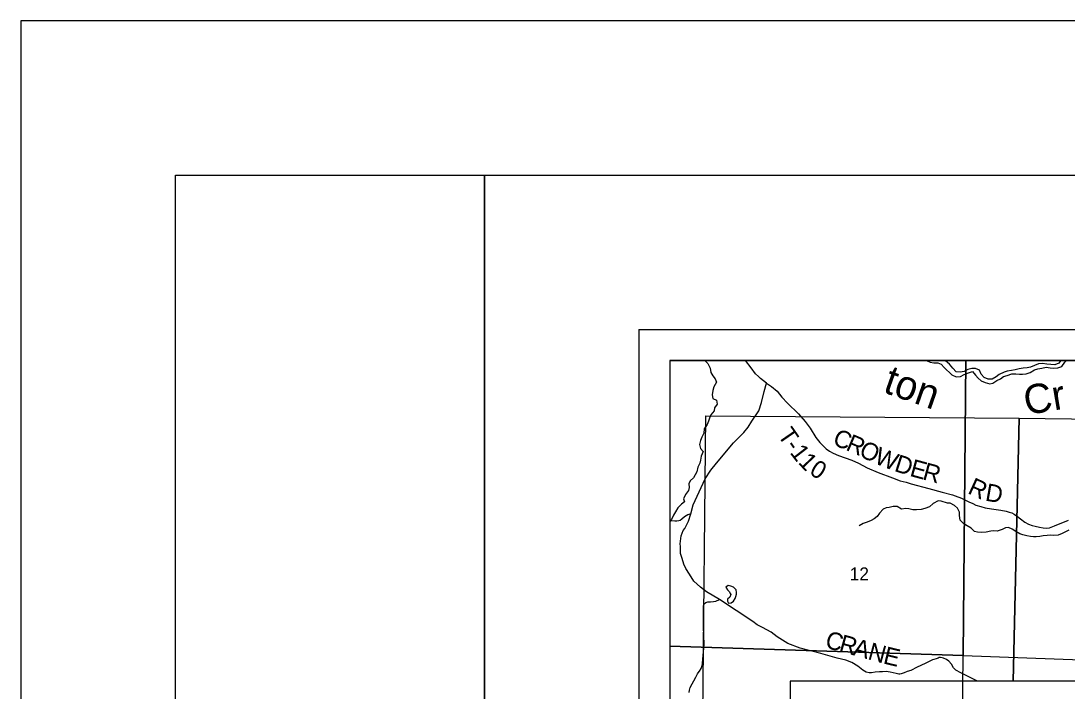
# Model space of a CAD drawing. Extents: x -19.9 to 41.9, y 0 to 32.3.
# Drawn here: x 0 to 3.386, y 19.829 to 22 of the extents above; entities that cross this region are included whole.
import ezdxf

# ---------------------------------------------------------------- set-up
doc = ezdxf.new("R2010")
doc.units = 0
for name, color, linetype in [('GM_X_Corporation', 7, 'Continuous'), ('GM_X_Major_River', 7, 'Continuous'), ('GM_X_Major_River_Text', 7, 'Continuous'), ('GM_X_Minor_Lake', 7, 'Continuous'), ('GM_X_Minor_River', 7, 'Continuous'), ('GM_X_Section', 7, 'Continuous'), ('GM_X_Section_Text', 7, 'Continuous'), ('GM_X_Township_Road', 7, 'Continuous'), ('GM_X_Township_Road_Text', 7, 'Continuous'), ('SH_Border', 7, 'Continuous'), ('SH_Cut_Line', 7, 'Continuous'), ('SH_Data', 7, 'Continuous'), ('SH_Text', 7, 'Continuous')]:
    doc.layers.add(name, color=color, linetype=linetype)

msp = doc.modelspace()

# ---------------------------------------------------------------- linework, layer by layer
at = {"layer": 'GM_X_Corporation'}
for points in [[(8.9, 17.8974), (8.9, 20.9), (2.1, 20.9), (2.1, 17.918), (2.4715, 17.9106), (2.973, 17.9007), (3.7505, 17.884), (3.984, 17.879), (4.2613, 17.8672), (4.9169, 17.8392), (5.0192, 17.8403), (5.0257, 17.9637), (5.4954, 17.9559), (5.761, 17.9543), (5.9048, 17.9534), (6.2397, 17.9517), (6.2497, 17.9517), (6.3069, 17.9505), (6.7, 17.9422), (6.9468, 17.937), (7.3858, 17.9277), (7.5529, 17.9242), (7.9072, 17.9171)], [(3.0583, 20.9), (2.1, 20.9), (2.1, 19.9743), (3.0491, 19.9448)], [(4.0724, 20.9), (3.0583, 20.9), (3.0491, 19.9448), (4.0503, 19.9079)], [(2.1, 19.9743), (2.1, 18.9334), (3.0393, 18.921), (3.0491, 19.9448)], [(3.0491, 19.9448), (4.0503, 19.9079), (4.0319, 18.9009), (3.0393, 18.921)]]:
    msp.add_lwpolyline(points, close=True, dxfattribs=at)
msp.add_lwpolyline([(7.9833, 20.9), (2.1, 20.9), (2.1, 17.918), (2.4715, 17.9106), (2.973, 17.9007), (3.7505, 17.884)], dxfattribs=at)
at = {"layer": 'GM_X_Major_River'}
for points in [[(2.9307, 20.9), (2.9424, 20.895), (2.955, 20.8926), (2.9675, 20.8921), (2.9783, 20.8884), (2.9883, 20.8772), (3.0131, 20.8534), (3.0268, 20.8475), (3.0409, 20.8485), (3.0533, 20.8548), (3.0673, 20.8596), (3.0798, 20.8643), (3.0891, 20.8524), (3.0984, 20.8423), (3.108, 20.8341), (3.1203, 20.829), (3.1359, 20.8247), (3.1458, 20.8268), (3.159, 20.835), (3.1699, 20.8408), (3.1796, 20.8478), (3.1925, 20.8514), (3.2069, 20.857), (3.2202, 20.8568), (3.2316, 20.8555), (3.2411, 20.8553), (3.254, 20.8563), (3.2669, 20.8607), (3.2804, 20.87), (3.2917, 20.8732), (3.3039, 20.8753), (3.3179, 20.8778), (3.3308, 20.8761), (3.343, 20.8748), (3.3559, 20.8766), (3.3692, 20.8806), (3.3784, 20.894), (3.384, 20.9)], [(3.3661, 20.9), (3.3591, 20.8918), (3.3463, 20.8863), (3.3329, 20.8872), (3.3204, 20.8885), (3.3066, 20.8905), (3.2934, 20.8892), (3.2809, 20.884), (3.2673, 20.8785), (3.2567, 20.876), (3.2442, 20.8754), (3.2305, 20.8729), (3.218, 20.8701), (3.2055, 20.868), (3.1919, 20.8651), (3.1821, 20.8623), (3.1666, 20.8548), (3.1568, 20.8474), (3.1433, 20.8396), (3.1308, 20.839), (3.1177, 20.8445), (3.1077, 20.8557), (3.1021, 20.8685), (3.0895, 20.874), (3.0777, 20.8738), (3.0652, 20.8713), (3.0524, 20.8639), (3.0395, 20.8622), (3.0273, 20.8635), (3.0157, 20.8754), (3.0049, 20.8881), (2.9921, 20.8985), (2.9891, 20.9)]]:
    msp.add_lwpolyline(points, dxfattribs=at)
at = {"layer": 'GM_X_Minor_Lake'}
for points in [[(2.2957, 20.1454), (2.2972, 20.1417), (2.2939, 20.1329), (2.2864, 20.1264), (2.2864, 20.1207), (2.2906, 20.1139), (2.2982, 20.1144), (2.3065, 20.1202), (2.3114, 20.1289), (2.314, 20.135), (2.3162, 20.1426), (2.3165, 20.1483), (2.315, 20.1566), (2.3065, 20.1657), (2.2974, 20.1686), (2.289, 20.1716), (2.2811, 20.1658)], [(2.2811, 20.1658), (2.2865, 20.1568), (2.2937, 20.1504), (2.2957, 20.1454)]]:
    msp.add_lwpolyline(points, dxfattribs=at)
at = {"layer": 'GM_X_Minor_River'}
for points in [[(2.2133, 20.9), (2.223, 20.8899), (2.2311, 20.8755), (2.2331, 20.8615), (2.2393, 20.8502), (2.247, 20.8404), (2.2516, 20.8298), (2.243, 20.815), (2.2389, 20.8028), (2.2375, 20.7891), (2.2392, 20.777), (2.2514, 20.7714), (2.2534, 20.7585), (2.2451, 20.7467), (2.2437, 20.7368), (2.2332, 20.7238), (2.2287, 20.7132), (2.2258, 20.7037), (2.2206, 20.6926), (2.2116, 20.6789), (2.2098, 20.6648), (2.2042, 20.6519), (2.1994, 20.6405), (2.1961, 20.6279), (2.1992, 20.6154), (2.2084, 20.6049), (2.2017, 20.59), (2.1995, 20.5775), (2.1974, 20.5672), (2.191, 20.5539), (2.1873, 20.5398), (2.1767, 20.52)], [(2.1767, 20.52), (2.1662, 20.5104), (2.1617, 20.5009), (2.1626, 20.4888), (2.1605, 20.4789), (2.1504, 20.4659), (2.1445, 20.4518), (2.1477, 20.4419), (2.1379, 20.435), (2.126, 20.4223), (2.1185, 20.4097), (2.1126, 20.3991), (2.1052, 20.3849), (2.1, 20.3779)], [(2.8098, 20.4238), (2.8003, 20.423), (2.7905, 20.418), (2.7784, 20.405), (2.7717, 20.3951), (2.7615, 20.387), (2.7517, 20.382), (2.7388, 20.3762), (2.7259, 20.3715), (2.7135, 20.3642)], [(3.3916, 20.35), (3.381, 20.3454), (3.3696, 20.3396), (3.3575, 20.3341), (3.3431, 20.3333), (3.3336, 20.3339), (3.3211, 20.3331), (3.3086, 20.3318), (3.2972, 20.3295), (3.2862, 20.3282), (3.2767, 20.3285), (3.2672, 20.3299), (3.2561, 20.3321), (3.2432, 20.3351), (3.2329, 20.338), (3.2196, 20.3455), (3.2085, 20.3533), (3.1967, 20.3585), (3.1864, 20.3577), (3.1758, 20.3523), (3.1599, 20.3476), (3.1485, 20.3483), (3.1386, 20.3474), (3.1235, 20.3435), (3.1102, 20.3426), (3.0961, 20.344), (3.0866, 20.3455), (3.0759, 20.3567), (3.0625, 20.3642), (3.0514, 20.3713), (3.0403, 20.3826), (3.0372, 20.3974), (3.0382, 20.4084), (3.0312, 20.422), (3.0213, 20.4306), (3.0079, 20.4373), (2.9984, 20.438), (2.9786, 20.4447), (2.9684, 20.445), (2.9529, 20.4372), (2.9401, 20.4257), (2.926, 20.4203), (2.9132, 20.4172), (2.8987, 20.4163), (2.8866, 20.4158), (2.874, 20.4191), (2.8645, 20.4205), (2.8497, 20.4181), (2.836, 20.4271), (2.823, 20.4274), (2.8098, 20.4238)]]:
    msp.add_lwpolyline(points, dxfattribs=at)
at = {"layer": 'GM_X_Section'}
for points in [[(2.4893, 19.7409), (2.2072, 19.7514), (2.2165, 20.721), (3.2305, 20.7127), (3.2116, 19.8611)], [(3.2116, 19.8611), (3.2305, 20.7127), (4.2465, 20.6998), (4.2277, 19.8611)]]:
    msp.add_lwpolyline(points, dxfattribs=at)
at = {"layer": 'GM_X_Township_Road'}
for points in [[(2.4132, 20.8267), (2.3938, 20.8418), (2.3867, 20.8483), (2.3776, 20.8565), (2.3631, 20.8757), (2.345, 20.9)], [(3.0961, 19.8611), (3.0416, 19.8877), (3.0262, 19.8964), (3.0187, 19.9048), (3.0121, 19.9161), (3.0028, 19.9255), (2.9952, 19.9311), (2.9857, 19.9357), (2.9812, 19.9371), (2.9766, 19.9376), (2.9719, 19.9373), (2.9683, 19.9362), (2.962, 19.934), (2.9551, 19.9317), (2.9506, 19.9299), (2.9419, 19.9261), (2.9262, 19.9189), (2.9012, 19.9064), (2.8798, 19.8962), (2.8683, 19.8923), (2.8582, 19.8884), (2.8488, 19.885), (2.8445, 19.884), (2.8409, 19.8843), (2.8326, 19.8858), (2.8228, 19.8877), (2.8128, 19.8902), (2.8006, 19.8923), (2.7888, 19.8917), (2.7787, 19.8912), (2.7649, 19.8904), (2.7525, 19.8882), (2.7457, 19.8878), (2.7361, 19.8902), (2.7252, 19.8963), (2.7082, 19.9093), (2.6897, 19.9218), (2.6698, 19.9287), (2.6413, 19.9362), (2.589, 19.9511), (2.522, 19.9678), (2.4823, 19.9837), (2.4474, 20.0049), (2.4286, 20.0201), (2.3998, 20.0351), (2.3827, 20.0439), (2.3692, 20.0548), (2.2614, 20.1254), (2.2191, 20.1504), (2.1993, 20.1659), (2.1776, 20.1852), (2.164, 20.2073), (2.1518, 20.2257), (2.1459, 20.24), (2.1398, 20.2588), (2.1348, 20.2744), (2.1346, 20.2878), (2.1346, 20.2972), (2.1341, 20.3059), (2.1344, 20.3151), (2.1368, 20.332), (2.1429, 20.3487), (2.1484, 20.356), (2.1604, 20.3791), (2.1679, 20.4028), (2.176, 20.432), (2.2147, 20.5164), (2.2329, 20.5446), (2.2511, 20.5676), (2.3058, 20.6329), (2.3398, 20.6669), (2.3536, 20.6839), (2.366, 20.7032), (2.3881, 20.7372), (2.3968, 20.7636), (2.4054, 20.799), (2.4132, 20.8267)], [(2.4132, 20.8267), (2.4289, 20.816), (2.4473, 20.8006), (2.4627, 20.7812), (2.481, 20.7616), (2.5165, 20.7268), (2.5386, 20.7018), (2.5541, 20.6811), (2.5727, 20.6503), (2.586, 20.6341), (2.5995, 20.6206), (2.6057, 20.6143), (2.6168, 20.6064), (2.6291, 20.5994), (2.6464, 20.5922), (2.6892, 20.5771), (2.7104, 20.5675), (2.7389, 20.5526), (2.7745, 20.5367), (2.8204, 20.52), (2.8458, 20.5106), (2.8649, 20.5054), (2.8808, 20.5004), (2.9387, 20.485), (2.9815, 20.4738), (3.0151, 20.4649), (3.0242, 20.4613), (3.0447, 20.4535), (3.0675, 20.4424), (3.0807, 20.4362), (3.0905, 20.4318), (3.1067, 20.4266), (3.1209, 20.423), (3.1411, 20.4189), (3.1715, 20.415), (3.1883, 20.4117), (3.1988, 20.4089), (3.2068, 20.4061), (3.2149, 20.4024), (3.2259, 20.3942), (3.2348, 20.3874), (3.2497, 20.3761), (3.2606, 20.37), (3.2724, 20.3658), (3.2829, 20.3635), (3.2969, 20.36), (3.3087, 20.3578), (3.3199, 20.357), (3.3289, 20.3584), (3.3457, 20.364), (3.3909, 20.3832)], [(2.1679, 20.4028), (2.158, 20.4005), (2.1478, 20.3939), (2.1394, 20.3861), (2.1333, 20.3816), (2.129, 20.3801), (2.123, 20.3796), (2.1166, 20.3794), (2.1037, 20.3803), (2.1, 20.3804)], [(2.1625, 19.825), (2.1635, 19.832), (2.1661, 19.8402), (2.1841, 19.8736), (2.1902, 19.8854), (2.1917, 19.8881), (2.1964, 19.8939), (2.202, 19.902), (2.2047, 19.9117), (2.206, 19.9187), (2.2066, 19.9325), (2.211, 19.9799), (2.2105, 20.0104), (2.209, 20.0377), (2.209, 20.1052), (2.2118, 20.1118), (2.2164, 20.1158), (2.2233, 20.118), (2.2314, 20.1187), (2.2415, 20.1188), (2.2495, 20.1203), (2.2614, 20.1254)]]:
    msp.add_lwpolyline(points, dxfattribs=at)
at = {"layer": 'SH_Border'}
for points in [[(0.5, 21.5), (1.5, 21.5), (1.5, 0.5), (0.5, 0.5)], [(1.5, 21.5), (33.5, 21.5), (33.5, 0.5), (1.5, 0.5)]]:
    msp.add_lwpolyline(points, close=True, dxfattribs=at)
at = {"layer": 'SH_Cut_Line'}
msp.add_lwpolyline([(0, 0), (34, 0), (34, 22), (0, 22)], close=True, dxfattribs=at)
at = {"layer": 'SH_Data'}
for p, q in [((2, 21), (9, 21)), ((2, 21), (2, 14)), ((2.1, 20.9), (2.1, 14.1)), ((2.1, 20.9), (8.9, 20.9))]:
    msp.add_line(p, q, dxfattribs=at)
at = {"layer": 'SH_Text'}
msp.add_lwpolyline([(2.4893, 19.3423), (4.3977, 19.3423), (4.3977, 19.8611), (2.4893, 19.8611)], close=True, dxfattribs=at)

# ---------------------------------------------------------------- texts
at = {"layer": 'GM_X_Major_River_Text'}
for s, height, rotation, p in [('ton', 0.0947, 340.6595, (2.7868, 20.7982)), ('Cr', 0.09471, 9.5544, (3.2537, 20.7228))]:
    msp.add_text(s, height=height, rotation=rotation, dxfattribs=at).set_placement(p)
at = {"layer": 'GM_X_Section_Text'}
msp.add_text('12', height=0.04186, rotation=0, dxfattribs=at).set_placement((2.6824, 20.1878))
at = {"layer": 'GM_X_Township_Road_Text'}
for s, rotation, p in [('T', 304.5697, (2.4474, 20.6582)), ('C', 337.4108, (2.6239, 20.6289)), ('R', 336.6474, (2.6668, 20.6111)), ('-', 304.8825, (2.4717, 20.6229)), ('1', 307.6149, (2.4868, 20.6014)), ('O', 333.2191, (2.7088, 20.593)), ('W', 338.5253, (2.7587, 20.5681)), ('1', 314.1011, (2.5128, 20.5684)), ('D', 342.2379, (2.8238, 20.5426)), ('0', 327.6955, (2.5485, 20.534)), ('E', 344.8007, (2.874, 20.5266)), ('R', 345.0105, (2.9153, 20.5154)), ('R', 335.172, (3.0612, 20.4708)), ('D', 350.0658, (3.1186, 20.4464)), ('C', 345.0081, (2.5998, 19.9705)), ('R', 344.5953, (2.6448, 19.9585)), ('A', 344.5938, (2.6898, 19.9461)), ('N', 344.6417, (2.7381, 19.9328)), ('E', 346.3372, (2.788, 19.9191))]:
    msp.add_text(s, height=0.0568, rotation=rotation, dxfattribs=at).set_placement(p)

doc.saveas('drawing.dxf')
